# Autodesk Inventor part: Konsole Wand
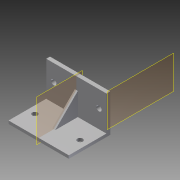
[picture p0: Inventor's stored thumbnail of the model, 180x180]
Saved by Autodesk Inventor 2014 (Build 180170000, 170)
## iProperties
Created: 2013-09
Part Number: Konsole Wand
Material: Stahl
Document SubType Name: Modeling
Designer: Stefan Tammegger
Mass: 2373.84 g
Surface Area: 785.988 cm^2
Volume: 302.4 cm^3
Density: 7.85 g/cm^3
Appearance: Stahl
Author: Stefan Tammegger
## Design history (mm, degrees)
workplane "Arbeitsebene1"
sketch "Skizze1"
  geometry: L1 (2743.717, 96)-(2743.717, 24) reference; L2 (2739.717, 20)-(2587.717, 20) reference; L3 (2583.717, 24)-(2583.717, 96) reference; L4 (2587.717, 100)-(2739.717, 100) reference; L5 (2583.717, 100)-(2573.717, 100); L6 (2573.717, 100)-(2573.717, 0); L7 (2573.717, 0)-(2583.717, 0); L8 (2583.717, 0)-(2583.717, 100); L9 (3800, 0)-(-80, 0) reference; 1 further point
  constraints: 8 end point, 2 collinear, 2 parallel, 1 horizontal, 1 perpendicular
  dimensions: "d0" = 10 distance of L7.end L6.end; "d1" = 100 distance of L6.end L5.end
extrude "Extrusion1" new body sketch "Skizze1" distance "d2" = 160; taper "d3" = 0 deg
sketch "Skizze2"
  geometry: L1 (0, 100)-(0, 0) reference; L2 (-160, 0)-(-160, 100) reference; L3 (0, 0)-(-160, 0) reference; L4 (-160, 8)-(0, 8); L5 (0, 8)-(0, 0); L6 (0, 0)-(-160, 0); L7 (-160, 0)-(-160, 8); 1 further point
  constraints: 8 end point, 3 collinear, 2 parallel, 1 horizontal, 1 perpendicular
  dimensions: "d5" = 8 distance of L4.end L5.end
extrude "Extrusion2" new body sketch "Skizze2" distance "d7" = 100; taper "d8" = 0 deg
workplane "Arbeitsebene2"
sketch "Skizze4"
  geometry: L1 (0, 0)-(160, 0) reference; L2 (0, 0)-(0, -100) reference; L3 (160, -100)-(0, -100) reference; L4 (160, 0)-(160, -100) reference; L5 (140, -80)-(20, -80); L6 (20, -80)-(20, -20); L7 (20, -20)-(140, -20); L8 (140, -20)-(140, -80); 3 further points
  constraints: 8 end point, 2 midpoint, 3 other
  dimensions: "d13" = 20 distance between parallel lines of L4 L8
hole "Bohrung1" sketch "Skizze4" at (20, -50), (140, -50) diameter "d14" = 14; stored, may be unused: countersink angle "d18" = 90 deg, drill point angle "d20" = 118 deg; dims "d15" = 6, "d16" = 4, "d17" = 2, "d19" = 8
sketch "Skizze5"
  geometry: L1 (0, 100)-(0, 0) reference; L2 (0, 100)-(-160, 100) reference; L3 (-160, 0)-(-160, 100) reference; L4 (0, 0)-(-160, 0) reference; L5 (200, 96)-(-4327.605, 96) reference; L6 (200, 24)-(-4345.557, 24) reference; L7 (-140, 80)-(-20, 80); L8 (-20, 80)-(-20, 20); L9 (-20, 20)-(-140, 20); L10 (-140, 20)-(-140, 80); L11 (-160, 56)-(0, 56); 3 further points
  constraints: 10 end point, 6 point on line, 1 perpendicular, 3 other
  dimensions: "d21" = 20 distance between parallel lines of L3 L10; "d22" = 40 distance between parallel lines of L11 L5
hole "Bohrung2" sketch "Skizze5" at (-140, 56), (-20, 56) diameter "d23" = 14; stored, may be unused: countersink angle "d27" = 90 deg, drill point angle "d29" = 118 deg; dims "d24" = 6, "d25" = 4, "d26" = 2, "d28" = 8
sketch "Skizze6"
  geometry: L1 (-100, 2573.717)-(0, 2573.717) reference; L2 (-8, 2573.717)-(-8, 2473.717) reference; L3 (-8, 2573.717)-(-68, 2573.717); L4 (-8, 2573.717)-(-8, 2513.717); L5 (-8, 2513.717)-(-68, 2573.717); 1 further point
  constraints: 6 end point, 2 point on line
  dimensions: "d30" = 60 distance of L2.start L3.end; "d31" = 60 distance of L2.start L4.end
extrude "Extrusion4" new body sketch "Skizze6" stored distance "d32" = 8; taper "d33" = 0 deg
node "Volumenkörper1"
node "Referenz1"
node "Referenz2"
node "Referenz3"
node "Referenz4"
node "Referenz5"
node "Volumenkörper3"
node "Referenz6"
node "Referenz7"
node "Volumenkörper4"
